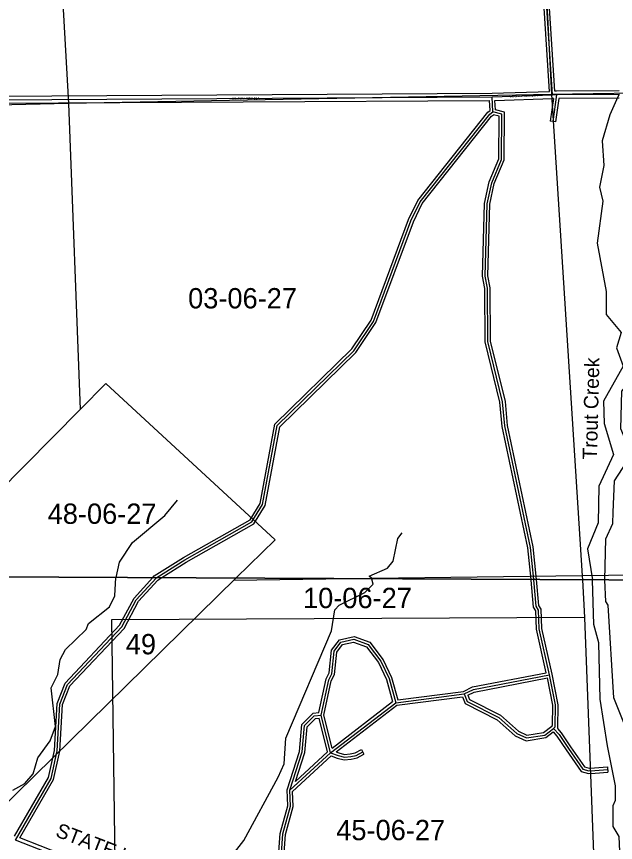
# Model space of a CAD drawing. Extents: x 418523 to 616617, y 1878279 to 2196743.
# Drawn here: x 470862 to 477490, y 2057555 to 2066699 of the extents above; entities that cross this region are included whole.
import ezdxf

# ---------------------------------------------------------------- set-up
doc = ezdxf.new("R2010")
doc.units = 0
for name, color, linetype in [('Level 1', 7, 'Continuous'), ('Level 2', 7, 'Continuous'), ('Level 22', 7, 'Continuous'), ('Level 23', 7, 'Continuous'), ('Level 28', 7, 'Continuous'), ('Level 31', 7, 'Continuous'), ('Level 32', 7, 'Continuous'), ('Level 34', 7, 'Continuous'), ('Level 41', 7, 'Continuous'), ('Level 5', 7, 'Continuous'), ('Level 63', 7, 'Continuous')]:
    doc.layers.add(name, color=color, linetype=linetype)

msp = doc.modelspace()

# ---------------------------------------------------------------- linework, layer by layer
at = {"layer": 'Level 1'}
for p, q in [((471138.041, 2071170.632), (471437.468, 2065734.681)), ((476503.859, 2071209.572), (476783.714, 2065835.738)), ((482107.939, 2065926.923), (476783.714, 2065835.738)), ((476783.714, 2065835.738), (471437.468, 2065734.681)), ((476783.714, 2065835.738), (477121.729, 2060505.571)), ((471437.468, 2065734.681), (466113.154, 2065629.497)), ((471437.468, 2065734.681), (471566.342, 2062349.19)), ((471566.342, 2062349.19), (471849.305, 2062638.174)), ((471849.305, 2062638.174), (473724.826, 2060905.248)), ((469734.731, 2060500.778), (471566.342, 2062349.19)), ((473724.826, 2060905.248), (473294.454, 2060483.356)), ((482419.845, 2060570.906), (477121.729, 2060505.571)), ((473294.456, 2060483.356), (468501.892, 2055785.221)), ((474795.826, 2060476.008), (473267.139, 2060456.577)), ((474795.826, 2060476.008), (474795.824, 2060476.008)), ((474795.824, 2060476.008), (474795.824, 2060476.008)), ((474795.828, 2060476.008), (474795.826, 2060476.008)), ((474795.831, 2060476.008), (474795.828, 2060476.008)), ((474795.835, 2060476.008), (474795.831, 2060476.008)), ((474795.841, 2060476.008), (474795.835, 2060476.008)), ((474795.849, 2060476.008), (474795.841, 2060476.008)), ((474795.859, 2060476.008), (474795.849, 2060476.008)), ((474795.874, 2060476.008), (474795.859, 2060476.008)), ((474795.895, 2060476.008), (474795.874, 2060476.008)), ((477121.729, 2060505.571), (474795.895, 2060476.008)), ((477121.729, 2060505.571), (477123.918, 2060464.615)), ((477123.92, 2060464.615), (477146.214, 2060047.494)), ((477146.214, 2060047.494), (471911.535, 2060020.41)), ((471911.535, 2060020.41), (471970.893, 2055899.513)), ((477146.214, 2060047.494), (477340.893, 2055098.836))]:
    msp.add_line(p, q, dxfattribs=at)
at = {"layer": 'Level 22'}
for p, q in [((476124.92, 2065809.928), (476791.934, 2065831.724)), ((476838.779, 2065831.856), (476791.934, 2065831.724)), ((477529.764, 2065836.455), (476838.779, 2065831.856)), ((471806.108, 2057209.764), (470849.03, 2057581.217))]:
    msp.add_line(p, q, dxfattribs=at)
msp.add_lwpolyline([(469956.628, 2065759.181), (470639.461, 2065778.238), (476124.92, 2065809.928)], dxfattribs=at)
at = {"layer": 'Level 23'}
for p, q in [((476124.153, 2065849.925), (476759.432, 2065870.684)), ((476838.514, 2065871.856), (476819.482, 2065871.802)), ((477529.498, 2065876.455), (476838.514, 2065871.856)), ((476156.755, 2065770.945), (476792.645, 2065791.724)), ((476802.704, 2065791.752), (476792.645, 2065791.725)), ((477530.03, 2065796.455), (476863.36, 2065792.017)), ((471820.099, 2057247.241), (470897.639, 2057605.259))]:
    msp.add_line(p, q, dxfattribs=at)
for points in [[(469955.512, 2065799.167), (470638.788, 2065818.236), (476124.152, 2065849.925)], [(469984.503, 2065719.941), (470640.135, 2065738.24), (476096.745, 2065769.762)]]:
    msp.add_lwpolyline(points, dxfattribs=at)
at = {"layer": 'Level 31'}
for p, q in [((476791.934, 2065831.724), (476722.392, 2066940.571)), ((476838.779, 2065831.856), (476796.498, 2065537.846)), ((476132.639, 2065642.96), (476124.92, 2065809.928)), ((475058.094, 2059102.751), (475817.095, 2059199.355)), ((474338.271, 2058547.728), (475058.094, 2059102.751)), ((474338.271, 2058547.728), (474232.087, 2058965.401)), ((476802.625, 2058818.8), (476824.236, 2058835.786)), ((473886.331, 2058133.213), (474338.271, 2058547.728))]:
    msp.add_line(p, q, dxfattribs=at)
for points in [[(472413.577, 2060487.668), (472723.691, 2060683.006), (473467.519, 2061104.406), (473585.289, 2061295.476), (473747.955, 2062170.043), (474594.125, 2062999.731), (474812.258, 2063323.774), (475226.143, 2064438.581), (475327.203, 2064646.831), (476098.967, 2065618.396), (476132.639, 2065642.96)], [(476586.055, 2060467.246), (476550.699, 2060822.468), (476265.473, 2062166.227), (476241.784, 2062432.924), (476078.269, 2063100.726), (476072.972, 2063692.827), (476048.624, 2063826.055), (476069.049, 2064626.419), (476120.214, 2064859.649), (476230.059, 2065117.321), (476232.534, 2065617.735), (476132.639, 2065642.96)], [(470849.03, 2057581.217), (471244.118, 2058262.927), (471312.481, 2058570.981), (471339.798, 2059087.634), (471424.473, 2059303.957), (472027.621, 2059943.159), (472187.419, 2060242.388), (472405.8, 2060482.767), (472413.579, 2060487.668)], [(476760.275, 2059411.444), (476645.968, 2059920.432), (476638.766, 2060128.857), (476613.964, 2060170.803), (476586.591, 2060461.882), (476586.057, 2060467.246)], [(474232.087, 2058965.401), (474317.302, 2059356.659), (474350.875, 2059423.045), (474377.133, 2059673.126), (474452.658, 2059772.761), (474594.646, 2059805.51), (474752.637, 2059746.169), (474893.546, 2059562.171), (474984.396, 2059370.059), (475058.094, 2059102.751)], [(475817.095, 2059199.355), (475917.377, 2059248.681), (476760.275, 2059411.444)], [(476824.236, 2058835.786), (476825.427, 2059077.628), (476760.275, 2059411.444)], [(475817.095, 2059199.355), (475850.238, 2059115.907), (476199.5, 2058938.883), (476398.708, 2058762.969), (476506.729, 2058712.246), (476706.969, 2058744.717), (476802.625, 2058818.8)], [(473886.331, 2058133.213), (474021.738, 2058557.676), (474048.209, 2058849.58), (474157.018, 2058957.412), (474232.087, 2058965.401)], [(476802.625, 2058818.8), (476865.925, 2058751.207), (476969.321, 2058597.224), (477130.592, 2058366.221), (477194.768, 2058347.721), (477261.909, 2058352.846), (477405.372, 2058363.051)], [(474338.271, 2058547.728), (474420.44, 2058518.951), (474490.312, 2058500.418), (474560.619, 2058505.521), (474619.257, 2058519.413), (474692.906, 2058559.777)], [(474008.431, 2056910.271), (473764.192, 2057008.596), (473808.881, 2057650.27), (473893.686, 2057958.246), (473886.331, 2058133.213)]]:
    msp.add_lwpolyline(points, dxfattribs=at)
at = {"layer": 'Level 32'}
for p, q in [((476819.481, 2065871.802), (476752.368, 2066941.921)), ((476759.432, 2065870.684), (476693.671, 2066919.223)), ((476101.927, 2065657.688), (476096.745, 2065769.762)), ((476161.58, 2065666.594), (476156.755, 2065770.946)), ((476802.704, 2065791.753), (476766.803, 2065542.117)), ((476863.361, 2065792.016), (476826.194, 2065533.575)), ((476826.194, 2065533.575), (476766.803, 2065542.117)), ((475069.963, 2059074.017), (475797.802, 2059166.656)), ((475080.105, 2059135.793), (475808.344, 2059228.482)), ((474356.101, 2058599.358), (475023.817, 2059114.203)), ((474400.406, 2058557.754), (475069.963, 2059074.017)), ((474356.101, 2058599.358), (474262.908, 2058965.932)), ((474304.778, 2058557.716), (474209.416, 2058932.817)), ((476784.086, 2058842.386), (476794.307, 2058850.419)), ((476846.884, 2058815.427), (476854.166, 2058821.151)), ((473916.891, 2058120.532), (474345.311, 2058513.475)), ((473949.204, 2058231.587), (474304.778, 2058557.716)), ((474678.486, 2058586.086), (474707.325, 2058533.469)), ((477403.243, 2058392.976), (477407.501, 2058333.126))]:
    msp.add_line(p, q, dxfattribs=at)
for points in [[(472369.911, 2060487.881), (472386.344, 2060505.971), (472708.294, 2060708.765), (473446.025, 2061126.711), (473556.817, 2061306.458), (473720.192, 2062184.836), (474570.942, 2063019.016), (474785.376, 2063337.564), (475198.521, 2064450.378), (475301.655, 2064662.904), (476078.004, 2065640.239), (476101.927, 2065657.689)], [(476616.219, 2060467.1), (476580.389, 2060827.082), (476295.196, 2062170.686), (476271.466, 2062437.846), (476108.237, 2063104.477), (476102.948, 2063695.678), (476078.694, 2063828.394), (476098.966, 2064622.789), (476148.916, 2064850.472), (476260.029, 2065111.121), (476262.651, 2065641.072), (476161.58, 2065666.594)], [(472469.433, 2060487.395), (472739.089, 2060657.249), (473489.014, 2061082.103), (473613.762, 2061284.493), (473775.719, 2062155.25), (474617.309, 2062980.446), (474839.139, 2063309.984), (475253.764, 2064426.783), (475352.75, 2064630.76), (476119.93, 2065596.553), (476138.946, 2065610.424)], [(476555.892, 2060467.394), (476521.009, 2060817.854), (476235.749, 2062161.77), (476212.103, 2062428.001), (476048.301, 2063096.975), (476042.995, 2063689.976), (476018.554, 2063823.716), (476039.131, 2064630.048), (476091.514, 2064868.826), (476200.088, 2065123.519), (476202.419, 2065594.396), (476138.946, 2065610.424)], [(470840.812, 2057626.867), (471215.834, 2058273.956), (471282.654, 2058575.051), (471310.095, 2059094.056), (471398.658, 2059320.313), (472003.047, 2059960.831), (472162.71, 2060259.806), (472369.913, 2060487.881)], [(470897.639, 2057605.259), (471272.401, 2058251.898), (471342.309, 2058566.911), (471369.501, 2059081.211), (471450.288, 2059287.601), (472052.195, 2059925.487), (472212.128, 2060224.971), (472425.253, 2060459.565), (472469.435, 2060487.395)], [(476724.228, 2059435.037), (476616.083, 2059916.595), (476609.047, 2060120.174), (476584.723, 2060161.311), (476556.731, 2060458.992), (476555.894, 2060467.394)], [(476789.641, 2059417.605), (476675.854, 2059924.271), (476668.485, 2060137.541), (476643.204, 2060180.295), (476616.453, 2060464.771), (476616.221, 2060467.1)], [(474207.382, 2058992.941), (474288.803, 2059366.783), (474321.614, 2059431.662), (474348.171, 2059684.581), (474435.319, 2059799.551), (474596.722, 2059836.777), (474771.231, 2059771.232), (474919.303, 2059577.88), (475012.626, 2059380.536), (475080.105, 2059135.793)], [(474262.908, 2058965.932), (474345.801, 2059346.535), (474380.136, 2059414.426), (474406.096, 2059661.671), (474469.997, 2059745.971), (474592.57, 2059774.242), (474734.044, 2059721.106), (474867.787, 2059546.463), (474956.164, 2059359.581), (475023.817, 2059114.203)], [(475808.344, 2059228.483), (475907.743, 2059277.376), (476724.228, 2059435.037)], [(475855.209, 2059184.667), (475927.012, 2059219.987), (476736.566, 2059376.309)], [(476794.308, 2058850.421), (476795.413, 2059074.801), (476736.566, 2059376.311)], [(476854.165, 2058821.151), (476855.442, 2059080.455), (476789.64, 2059417.605)], [(475797.802, 2059166.656), (475826.547, 2059094.281), (476182.516, 2058913.858), (476382.069, 2058737.638), (476502.375, 2058681.148), (476719.304, 2058716.325), (476799.399, 2058778.354)], [(475855.209, 2059184.667), (475873.93, 2059137.534), (476216.482, 2058963.909), (476415.347, 2058788.3), (476511.084, 2058743.346), (476694.633, 2058773.109), (476784.255, 2058842.519)], [(473856.134, 2058137.264), (473992.157, 2058563.661), (474019.319, 2058863.186), (474143.376, 2058986.131), (474207.382, 2058992.941)], [(473949.204, 2058231.587), (474051.319, 2058551.691), (474077.099, 2058835.973), (474170.66, 2058928.693), (474209.416, 2058932.817)], [(476846.884, 2058815.427), (476889.48, 2058769.945), (476994.077, 2058614.174), (477149.11, 2058392.105), (477197.88, 2058378.046), (477259.703, 2058382.766), (477403.243, 2058392.976)], [(476799.399, 2058778.354), (476842.37, 2058732.47), (476944.566, 2058580.274), (477112.075, 2058340.336), (477191.657, 2058317.395), (477264.116, 2058322.926), (477407.501, 2058333.126)], [(474345.311, 2058513.475), (474411.622, 2058490.251), (474487.476, 2058470.132), (474565.192, 2058475.774), (474630.12, 2058491.155), (474707.325, 2058533.469)], [(474400.407, 2058557.754), (474429.256, 2058547.65), (474493.15, 2058530.704), (474556.046, 2058535.269), (474608.395, 2058547.671), (474678.486, 2058586.086)], [(473997.226, 2056882.441), (473732.749, 2056988.915), (473779.161, 2057655.344), (473863.515, 2057961.68), (473856.134, 2058137.264)], [(474019.634, 2056938.101), (473795.636, 2057028.279), (473838.601, 2057645.195), (473923.857, 2057954.811), (473916.891, 2058120.533)]]:
    msp.add_lwpolyline(points, dxfattribs=at)
at = {"layer": 'Level 5'}
for p, q in [((471963.566, 2060485.006), (471964.588, 2060489.866)), ((474798.035, 2060470.758), (474792.63, 2060476.024)), ((477235.622, 2060464.068), (477236.499, 2060458.666)), ((477371.752, 2060460.468), (477371.837, 2060463.401))]:
    msp.add_line(p, q, dxfattribs=at)
for points in [[(477529.764, 2065836.455), (477517.293, 2065810.695), (477427.05, 2065610.386), (477342.716, 2065324.583), (477360.995, 2065051.004), (477311.697, 2064809.761), (477350.18, 2064653.916), (477287.75, 2064188.711), (477386.109, 2063656.523), (477387.068, 2063400.85), (477552.588, 2063201.103), (477500.153, 2063030.43), (477576.709, 2062827.483), (477357.663, 2062441.602), (477364.36, 2062194.266), (477468.083, 2061850.44), (477304.917, 2061499.926), (477297.222, 2061093.731), (477180.258, 2060805.181), (477235.62, 2060464.068)], [(477465.901, 2061212.917), (477479.634, 2061559.801), (477614.241, 2061767.53), (477606.799, 2061992.686), (477549.25, 2062134.804), (477559.527, 2062551.533), (477651.897, 2062667.821), (477794.197, 2062767.136)], [(471964.586, 2060489.866), (472000.219, 2060659.387), (472143.764, 2060874.688), (472504.584, 2061175.811), (472641.871, 2061344.231)], [(477371.835, 2060463.401), (477384.997, 2060918.37), (477460.84, 2061084.926), (477465.901, 2061212.917)], [(474792.628, 2060476.024), (474764.639, 2060503.292), (474967.051, 2060592.112), (475028.53, 2060668.907), (475080.759, 2060922.133), (475130.45, 2060984.076)], [(470821.519, 2058134.076), (470955.291, 2058208.38), (471047.581, 2058316.264), (471098.549, 2058491.059), (471232.969, 2058682.075), (471292.177, 2058840.14), (471244.447, 2059265.559), (471320.296, 2059415.224), (471346.184, 2059581.788), (471405.133, 2059689.861), (471631.425, 2059913.73), (471656.794, 2059980.262), (471891.186, 2060162.42), (471950.235, 2060287.134), (471959.641, 2060487.178)], [(472212.247, 2056317.554), (472547.111, 2056574.185), (472731.451, 2056748.261), (473377.831, 2057578.401), (473756.736, 2058276.622), (473824.246, 2058426.317), (473842.451, 2058709.654), (474349.04, 2059899.04), (474383.626, 2060132.286), (474433.947, 2060182.048), (474718.131, 2060322.226), (474810.321, 2060413.439), (474793.98, 2060471.86)], [(476680.234, 2054701.151), (476882.112, 2055033.531), (477251.233, 2055465.057), (477310.401, 2055614.781), (477280.788, 2056306.867), (477474.416, 2056655.939), (477534.142, 2056914.076), (477501.818, 2057097.64), (477537.092, 2057455.909), (477529.639, 2057622.702), (477463.536, 2057731.434), (477464.811, 2057964.85), (477490.111, 2058023.041), (477490.968, 2058181.436), (477401.647, 2058623.755), (477321.066, 2059141.066), (477307.794, 2059766.351), (477250.519, 2059966.754), (477236.499, 2060458.666)], [(477788.554, 2057712.988), (477697.798, 2057888.541), (477708.66, 2058355.352), (477611.039, 2058806.032), (477471.219, 2059156.918), (477410.058, 2060182.651), (477385.277, 2060224.462), (477371.752, 2060460.468)]]:
    msp.add_lwpolyline(points, dxfattribs=at)
at = {"layer": 'Level 63'}
for points in [[(458389.486, 2060556.305), (497959.303, 2060362.642), (498157.219, 2105821.853), (458637.192, 2106016.114), (458389.486, 2060556.305)], [(458142.926, 2015097.576), (497762.103, 2014904.337), (497959.305, 2060362.642), (458389.488, 2060556.305), (458142.926, 2015097.576)]]:
    msp.add_lwpolyline(points, dxfattribs=at)

# ---------------------------------------------------------------- texts
at = {"layer": 'Level 2'}
for s, p in [('03-06-27', (472761.064, 2063467.791)), ('48-06-27', (471207.034, 2061082.431)), ('10-06-27', (474032.908, 2060149.494)), ('49', (472071.401, 2059638.153)), ('45-06-27', (474400.469, 2057580.341))]:
    msp.add_text(s, height=225, dxfattribs=at).set_placement(p)
at = {"layer": 'Level 28'}
msp.add_text('STATE HWY 13', height=160, rotation=338.7872806, dxfattribs=at).set_placement((471283.141, 2057626.163))
at = {"layer": 'Level 34'}
for height, rotation, p in [(24.99916, 1.8707361, (476318.994, 2065803.767)), (25, 0.3301749, (473242.343, 2065780.777))]:
    msp.add_text('COUNTY HWY 16A', height=height, rotation=rotation, dxfattribs=at).set_placement(p)
at = {"layer": 'Level 41'}
msp.add_text('Trout Creek', height=160, rotation=88.5864083, dxfattribs=at).set_placement((477285.427, 2061792.226))

doc.saveas('drawing.dxf')
